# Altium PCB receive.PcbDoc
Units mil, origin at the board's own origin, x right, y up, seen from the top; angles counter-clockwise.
Board outline 787 x 1403 mil, 2 copper layers (Top Layer, Bottom Layer); 26 components, 20 nets, 101 pads, 164 vias.
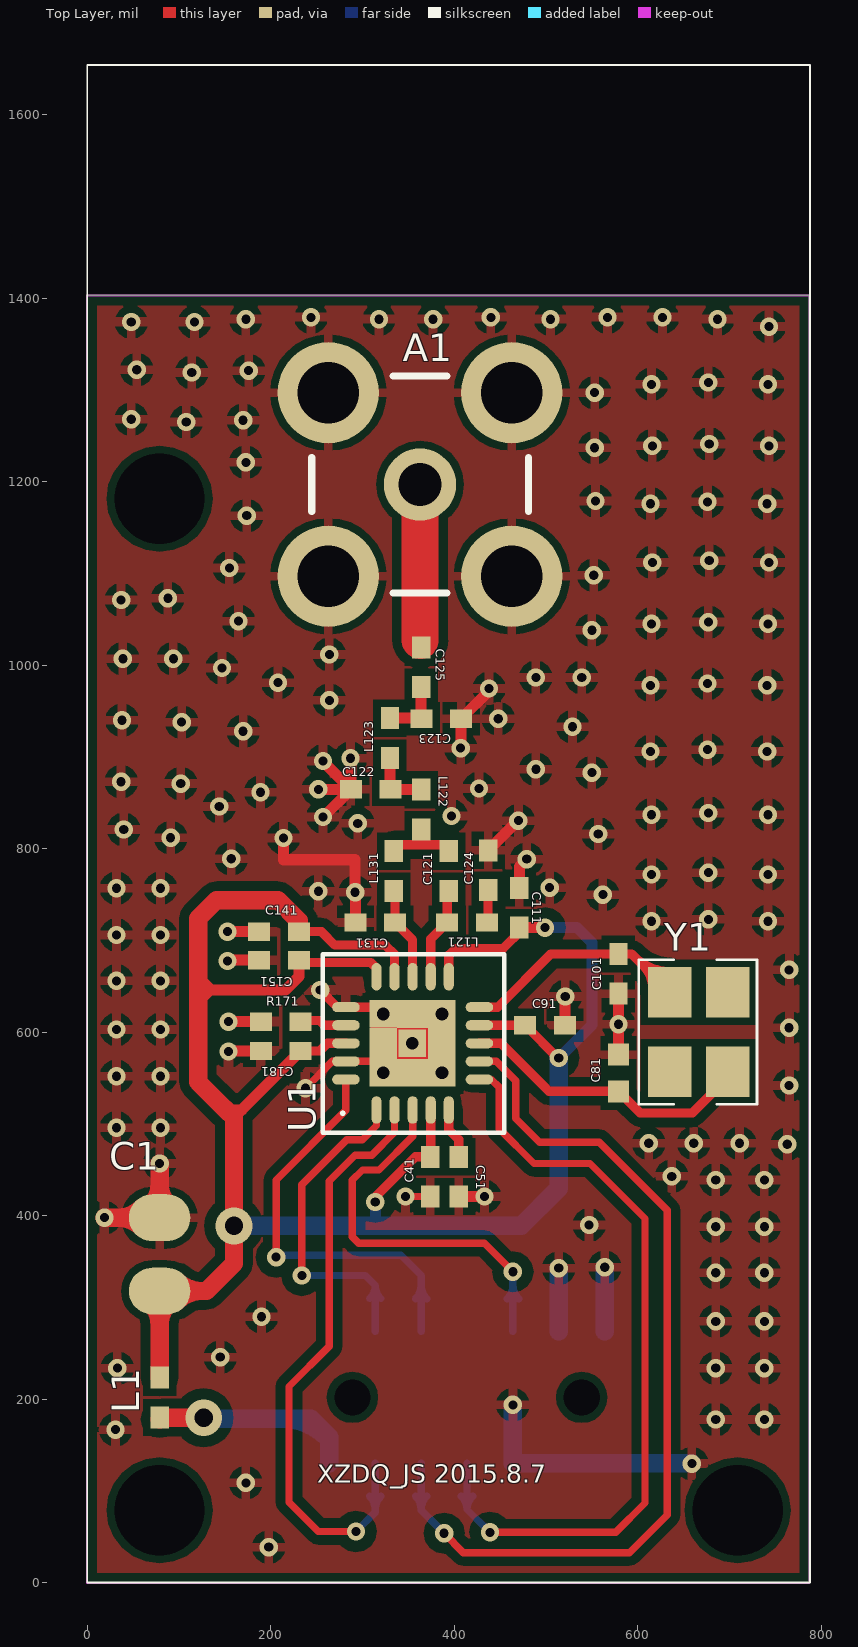
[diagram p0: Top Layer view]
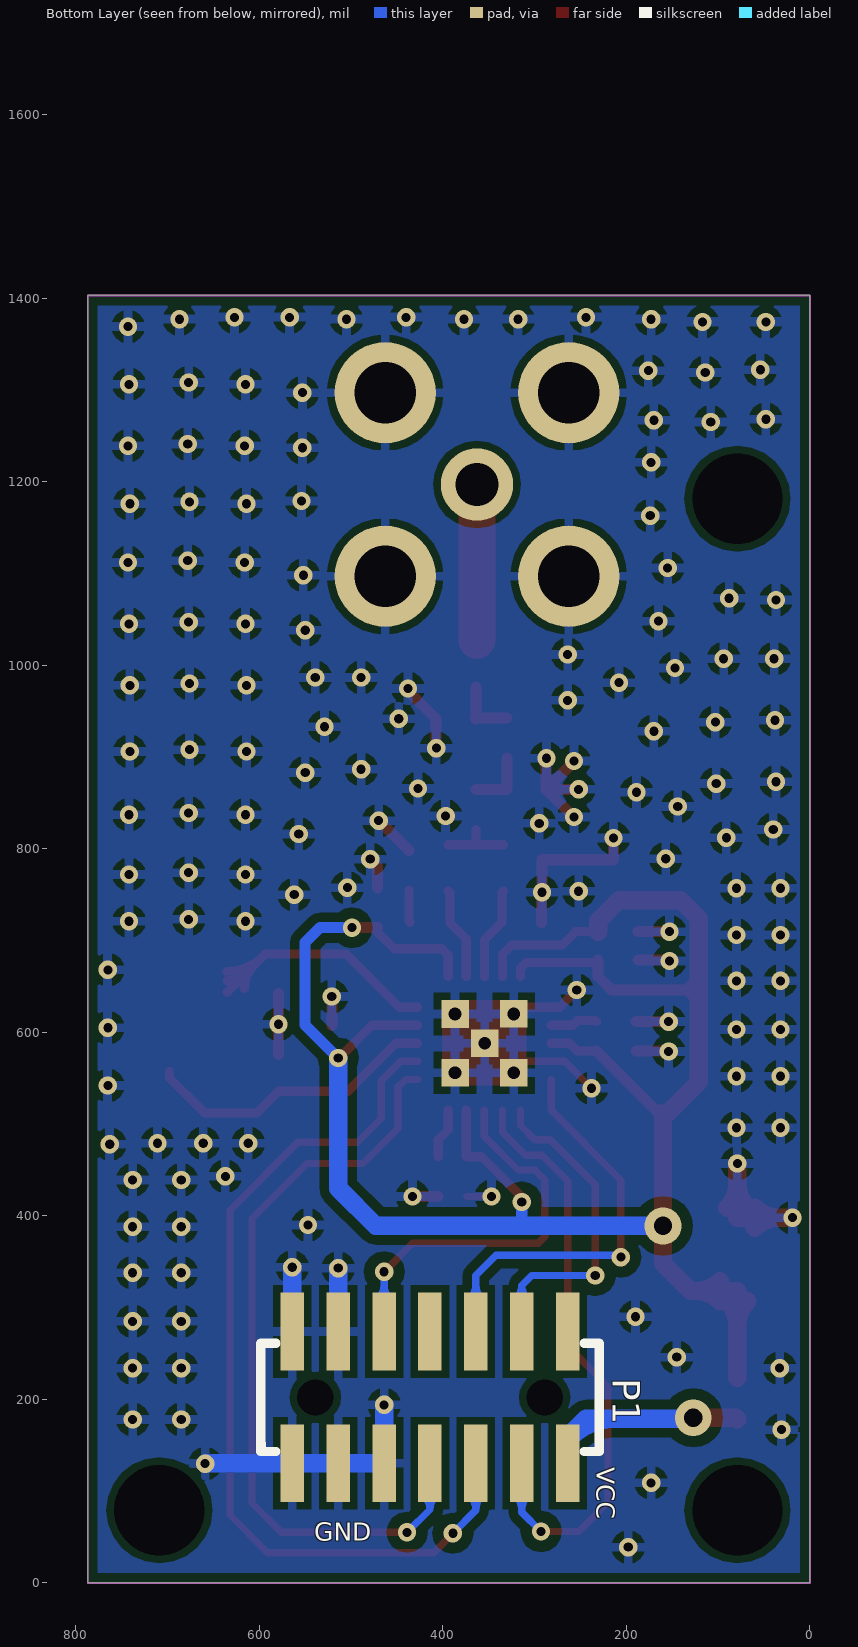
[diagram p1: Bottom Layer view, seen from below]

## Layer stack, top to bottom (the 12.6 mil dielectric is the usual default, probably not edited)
Top Layer: signal copper 1.4
Dielectric: dielectric 12.6, FR-4, Dk 4.8
Bottom Layer: signal copper 1.4

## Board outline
0,0 787,0 787,1403 0,1403

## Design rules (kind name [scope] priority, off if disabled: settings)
Clearance InPolygon_GND_P1 [InNamedPolygon('GND_P1') vs InNet('GND')] p1: gap=8
Clearance InPolygon_GND_P2 [InNamedPolygon('GND_P2') vs InNet('GND')] p2: gap=8
Clearance InPolygon_GND [InNamedPolygon('GND') vs InNet('GND')] p3: gap=8
Clearance "InPolygon_GND layer1" [InNamedPolygon('GND layer1') vs InNet('GND')] p4: gap=8
Clearance CopperToBoard [InPolygon vs (IsTrack Or IsArc) And OnLayer('Keep-out Layer')] p5: gap=10
Clearance ViaToCopper [IsVia vs InPolygon] p6: gap=12
Clearance ViaToVia [IsVia vs IsVia] p7: gap=8
Clearance PadToCopper [IsPad vs InPolygon] p8: gap=8
Clearance PadToVia [IsPad vs IsVia] p9: gap=8
Clearance CPadToPad [IsPad vs IsPad] p10: gap=8
Clearance RouteToPad_1 [IsTrack or IsArc vs IsVia] p11: gap=8
Clearance RouteToPad [IsTrack Or IsArc vs IsPad] p12: gap=8
Clearance RouteToRoute [IsTrack or IsArc vs IsTrack or IsArc] p13: gap=8
Clearance [All] p14: gap=10
ComponentClearance [All] p1: gap=0 collisioncheckmode=3 verticalgap=0 showdistances=FALSE
MinimumSolderMaskSliver [All] p1: minsoldermaskwidth=0
PolygonConnect [All] p1: connectstyle=Relief reliefconductorwidth=10 reliefentries=4 polygonreliefangle="90 Angle"
RoutingVias [All] p1: holewidth=28 width=50 viastyle="Through Hole" minholewidth=10 minwidth=20 maxholewidth=28 maxwidth=50
SilkToSilkClearance [All] p1: silktosilkclearance=0
SilkscreenOverComponentPads [All] p1: minsilkscreentomaskgap=0
SolderMaskExpansion [All] p1: expansion=4
Width [All] p1: maxlimit=60 minlimit=8 preferedwidth=10
24 further rules are at their usual default settings.

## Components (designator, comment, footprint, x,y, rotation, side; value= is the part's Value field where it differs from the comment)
A1 "Antenna" SMA 363,1197 r0 top
C1 "1uF" "0805 (reflow)" 80,358 r90 top
C41 "100nF" "0402 (REFLOW)" 374,442.65 r270 top
C51 "100nF" "0402 (REFLOW)" 405,442.65 r270 top
C81 "12pF" "0402 (REFLOW LF)" 578,555.65 r90 top
C91 "10nF" "0402 (REFLOW)" 499,607.65 r0 top
C101 "15pF" "0402 (REFLOW)" 579,663.65 r270 top
C111 "220pF" "0402 (REFLOW)" 471,735.65 r90 top
C121 "3.9pF" "0402 (REFLOW)" 394,775.65 r90 top
C122 "8.2pF" "0402 (REFLOW)" 309,864.65 r180 top
C123 "5.6pF" "0402 (REFLOW)" 386,941.65 r0 top
C124 "220pF" "0402 (REFLOW)" 437,776.65 r270 top
C125 "220pF" "0402 (REFLOW)" 364,997.65 r90 top
C131 "3.9pF" "0402 (REFLOW)" 314,719.65 r180 top
C141 "10nF" "0402 (REFLOW)" 209,709.65 r180 top
C151 "220pF" "0402 (REFLOW)" 209,678.65 r180 top
C181 "220pF" "0402 (REFLOW)" 211,579.65 r180 top
L1 "LM15HG102SN1D" "0402 (REFLOW)" 79,202 r270 top
L121 "27nH" "0402 (REFLOW)" 414,719.65 r0 top
L122 "22nH" "0402 (REFLOW)" 364,842.65 r270 top
L123 "27nH" "0402 (REFLOW)" 330,920.65 r270 top
L131 "27nH" "0402 (REFLOW)" 334,775.65 r270 top
P1 "Header 7X2" "SFM SMD Socket 2x7 b" 289,202.3 r270 bottom locked
R171 "56K" "0402 (REFLOW)" 211,611.65 r180 top
U1 "CC1101" QLP20/QFN/CC1101 353.18,587.57 r90 top
Y1 "26MHz" "XTAL_SMD_3_2x2_5 (3.2 x 2.5 mm)" 695.99,558.04 r90 top

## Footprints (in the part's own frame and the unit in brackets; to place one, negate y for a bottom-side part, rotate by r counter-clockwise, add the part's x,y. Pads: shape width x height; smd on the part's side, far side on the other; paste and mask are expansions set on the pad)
"0402 (REFLOW LF)" [mil]
  rect 24x23 smd paste+0 mask+6: 1(-20,-1) 2(20,-1)
"0402 (REFLOW)" [mil]
  rect 24x20 smd paste+0 mask+4: 1(-21.65,0) 2(21.65,0)
"0805 (reflow)" [mil]
  oval 51x67 smd paste+0 mask+4: 1(-40,1) 2(40,1)
QLP20/QFN/CC1101 [mil]
  oval 30x11 smd paste-2 mask+2: 1(-72.24,37.83) 2(-72.24,18.14) 3(-72.24,-1.54) 4(-72.24,-21.23) 5(-72.24,-40.91) 11(73.05,-40.91) 12(73.05,-21.23) 13(73.05,-1.54) 14(73.05,18.14) 15(73.05,37.83)
  oval 11x30 smd paste-2 mask+2: 6(-38.97,-74.27) 7(-19.28,-74.27) 8(0.4,-74.27) 9(20.09,-74.27) 10(39.77,-74.27) 16(39.77,71.18) 17(20.09,71.18) 18(0.4,71.18) 19(-19.28,71.18) 20(-38.97,71.18)
  rect 30x30 / inner round 60 / far side rect 30x30 hole 14 paste+0 mask+0: 21(-31.66,30.48) 22(32.37,30.48) 23(-31.66,-33.52) 24(32.34,-33.52) 25(0.4,-1.15)
  rect 34x30 smd paste-13 mask+0: 26(0.34,30.48) 29(0.37,-33.52)
  rect 30x34 smd paste-13 mask+0: 27(32.34,-1.58) 28(-31.66,-1.52)
  silkscreen extent -97,-101 98,96
"SFM SMD Socket 2x7 b" [mm]
  round 0.8 hole 1 unplated: 0(0.003,0) 0(0.004,-6.35)
  rect 2.15x0.65 smd: 1(-1.821,0.635) 2(1.829,0.635) 3(-1.821,-0.635) 4(1.829,-0.635) 5(-1.821,-1.905) 6(1.829,-1.905) 7(-1.821,-3.175) 8(1.829,-3.175) 9(-1.821,-4.445) 10(1.829,-4.445) 11(-1.821,-5.715) 12(1.829,-5.715) 13(-1.821,-6.985) 14(1.829,-6.985)
  silkscreen extent -1.5,-7.86 1.5,1.51
SMA [mm]
  round 2 hole 1.2: 1(-0.005,-0.002)
  round 2.8 hole 1.7: 2(-2.545,-2.542) 3(2.535,-2.542) 4(2.535,2.538) 5(-2.545,2.538)
  silkscreen extent -3.01,-3 2.99,3
"XTAL_SMD_3_2x2_5 (3.2 x 2.5 mm)" [mm]
  rect 1.4x1.2 smd paste-0.06 mask+0.05: 1(-0.025,-0.051) 2(2.175,-0.051) 3(2.175,1.549) 4(-0.025,1.549)
  silkscreen extent -0.93,-0.86 3.07,2.41

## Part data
C1 C41 C51 C81 C91 C101 C111 C121 C122 C123 C124 C125 C131 C141 C151 C181: library part CAP, "CAP"
L1 L121 L122 L123 L131: library part Inductor, "Inductor"
P1: "Header, 7-Pin, Dual row"
R171: library part RES, "RES"
U1: "Single chip transceiver"
Y1: library part XY1, "四脚晶振"

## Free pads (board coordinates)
  round 39.37 hole 98.43: 0(78.96,79.12) 0(78.96,1181.48) 0(708.88,79.12)

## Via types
v1: diameter 20, hole 10, Top Layer to Bottom Layer, 162 vias
v2: diameter 40, hole 20, Top Layer to Bottom Layer, 2 vias

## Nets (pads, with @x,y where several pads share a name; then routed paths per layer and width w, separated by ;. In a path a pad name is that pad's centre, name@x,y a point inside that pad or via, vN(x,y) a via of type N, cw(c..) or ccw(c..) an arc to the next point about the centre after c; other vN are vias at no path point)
230: C81.1 U1.8 Y1.1 | length 324.5
  Top Layer w10: U1.8 451.03,587.97 503.35,535.65 C81.1 602.65,512 659.53,512 697.99,550.47 Y1.1
233: C101.1 U1.10 Y1.3 | length 343.2
  Top Layer w10: U1.10 447.34,627.34 505.31,685.31 C101.1 593.35,685.31 Y1.3 ; 596.49,682.16 ccw(c635,720.67) Y1.3@635,666.21 ; 605.99,672.66 cw(c580.93,647.59) Y1.3@616.38,647.59 ; Y1.3@613.56,665.09 ccw(c635,686.53) Y1.3@635,656.21
246: R171.1 U1.17 | length 52.1
  Top Layer w10: R171.1 234,613 253,613 258.35,607.65 U1.17
254: C122.1 L122.1 L123.2 | length 68.1
  Top Layer w12: L123.2 330,865.31 C122.1 331,864.31 L122.1
255: C123.1 C125.1 L123.1 | length 69.1
  Top Layer w12: L123.1 363.69,942.31 C123.1 364,942 C125.1
256: A1.1 C125.2 | length 171.7
  Top Layer w40: A1.1 362.8,1027.2 C125.2@363,1027
  Top Layer w50: A1.1 A1.1@364,1195.72
275: C51.1 U1.5 | length 55.5
  Top Layer w10: U1.5 394.09,493.91 405,483 C51.1
286: C131.1 L131.2 U1.13 | length 102
  Top Layer w10: L131.2 335.65,752.35 C131.1 354.72,700.58 U1.13
287: C121.2 L122.2 L131.1 | length 76.7
  Top Layer w10: L131.1@334,804.31 C121.2@394,804.31 ; 364,804.31 L122.2
290: C121.1 L121.1 U1.12 | length 101.5
  Top Layer w10: U1.12 374.41,701.72 L121.1 392.35,752.35 C121.1
291: C124.2 L121.2 | length 35.9
  Top Layer w10: L121.2 437,721 C124.2
CC1101_CSN: P1.6 U1.7 | length 1016.5
  Top Layer w8: v1(389,54) 410,33 419,33 591,33 632,74 632,406 558,480 493,480 467,506 467,547 445.72,568.28 U1.7
  Bottom Layer w8: P1.6@357.78,94.55 cw(c342.77,79.54) 364,79.54 cw(c385.23,79.54) P1.6@370.22,94.55 ; P1.6 364,79 v1(389,54)
CC1101_GDO0: P1.8 U1.6 | length 879.9
  Top Layer w8: U1.6 440.4,548.6 449,540 449,495 487,457 548,457 608,397 608,87 576,55 v1(439,55)
  Bottom Layer w8: P1.8@407.88,94.46 cw(c393.87,80) 414,80 ; P1.8 414,80 ; P1.8@420.12,94.46 ccw(c434.13,80) 414,80 ; v1(439,55) 414,80
CC1101_GDO2: P1.9 U1.3 | length 465.2
  Top Layer w8: U1.3 354.72,486.72 318,450 300,450 289,439 289,377 296,370 430,370 433,370 v1(464,339)
  Bottom Layer w8: P1.9@457.78,309.75 ccw(c442.77,324.76) 464,324.76 ccw(c485.23,324.76) P1.9@470.22,309.75 ; P1.9 v1(464,339)
CC1101_SCLK: P1.3 U1.1 | length 390.1
  Top Layer w8: v1(234,335) 234,434 283,483 300,483 315.35,498.35 U1.1
  Bottom Layer w8: v1(234,335) 303,335 314,324 ; P1.3@307.95,309.91 ccw(c294.57,324) 314,324 ; P1.3 314,324 ; P1.3@320.05,309.91 cw(c333.43,324) 314,324
CC1101_SI: P1.5 U1.20 | length 487.4
  Top Layer w8: v1(206,355) 206,439 282,515 U1.20
  Bottom Layer w8: v1(206,355) 208,357 342,357 364,335 P1.5 ; P1.5@357.78,309.75 ccw(c342.77,324.76) 364,324.76 ccw(c385.23,324.76) P1.5@370.22,309.75
CC1101_SO: P1.4 U1.2 | length 688.1
  Top Layer w8: v1(293,56) 252,56 220,88 220,214 264,258 264,365 264,438 292,466 310,466 335.04,491.04 U1.2
  Bottom Layer w8: v1(293,56) 314,77 P1.4 ; P1.4@307.78,94.55 cw(c292.77,79.54) 314,79.54 cw(c335.23,79.54) P1.4@320.22,94.55
GND: A1.2 A1.3 A1.4 A1.5 C1.2 C41.2 C51.2 C81.2 C91.2 C101.2 C111.2 C122.2 C123.2 C124.1 C131.2 C141.2 C151.2 C181.2 P1.10 P1.11 P1.12 P1.13 P1.14 R171.2 U1.16 U1.19 U1.21 U1.22 U1.23 U1.24 U1.25 U1.26 U1.27 U1.28 U1.29 | length 1593.6
  Top Layer w8: v1(238,539) 267.28,568.28 U1.19 310.32,568.28 U1.21 ; v1(347,421) C41.2
  Top Layer w10: v1(254,646) 272.66,627.34 U1.16 315.3,627.34 U1.22
  Top Layer w12: v1(153,677.65) 154,678.65 C151.2 ; v1(153,709.65) C141.2 ; v1(154,579) 154.65,579.65 C181.2 ; v1(154,611.65) R171.2 ; v1(214,811.65) 214,788 292,788 v1(292,752.65) 292.35,752.31 C131.2 ; v1(252,864.65) C122.2 ; v1(257,834.65) 257.35,834.65 C122.2 ; v1(257,895.65) 257,895 C122.2 ; v1(287,898.65) 287.35,898.31 C122.2 ; C51.2 v1(433,421) ; v1(407,909.65) 407.65,910.31 C123.2 438,972 v1(438,974.65) ; C124.1 469.35,830.65 v1(470,830.65) ; C111.2 471,780.65 v1(479,788.65) ; C91.2 520.65,638.65 v1(521,639) ; C81.2 v1(579,608.65) C101.2
  Top Layer w20: v1(19,398) C1.2 v1(79,457) ; C1.2@60.04,387.04 ccw(c33.58,360.58) 33.58,398 ccw(c33.58,435.42) C1.2@60.04,408.96 ; C1.2@68.04,408.96 ccw(c41.58,435.42) 79,435.42 ccw(c116.42,435.42) C1.2@89.96,408.96
  Bottom Layer w20: v1(464,194) P1.10 P1.14 658.7,130.3 v1(659,130) ; P1.11 v1(514,343) ; P1.13 v1(564,344)
  other v1: 198,39 173,109 31,167 685,178 738,178 33,234 685,234 738,234 145,246 685,285 738,285 190,290 685,338 738,338 685,388 738,388 547,390 685,439 738,439 637,443 763,478 612,479 661,479 711,479 32,496 80,496 765,542 32,552 80,552 32,603 80,603 765,605 32,656 80,656 765,668 32,706 80,706 615,721 742,721 677,723 562,750 252,753.65 32,757 80,757 504,757.65 615,772 742,772 677,774 157,789 91,812 557,816 40,821 295,827.65 397,835.65 615,837 742,837 677,839 144,846 189,861.65 427,865.65 102,871 37,873 550,883 489,886.65 614,906 741,906 676,908 170,928 529,933 103,938 38,940 448,941.65 264,961.65 614,978 741,978 676,980 208,981 489,986.65 539,986.65 147,997 39,1007 94,1007 264,1011.65 550,1038 615,1045 742,1045 677,1047 165,1048 37,1071 88,1073 552,1098 155,1106 616,1112 743,1112 678,1114 174,1163 614,1176 741,1176 676,1178 554,1179 173,1221 553,1237 616,1239 743,1239 678,1241 108,1265 170,1267 48,1268 553,1297 615,1306 742,1306 677,1308 114,1319 176,1321 54,1322 743,1369 48,1374 117,1374 173,1377 318,1377 377,1377 505,1377 687,1377 244,1379 440,1379 567,1379 627,1379
VCC: L1.2 P1.2 | length 279.4
  Top Layer w20: L1.2@79,178.35 80.65,180 v2(127,180)
  Bottom Layer w20: v2@127,179 244,179 264,159 P1.2 ; 210.96,179 cw(c210.96,106.79) P1.2@262.02,157.85
VDD: C1.1 C41.1 C91.1 C111.1 C141.1 C151.1 C181.1 L1.1 U1.4 U1.9 U1.11 U1.14 U1.15 U1.18 | length 2571.9
  Top Layer w10: C151.1 233.31,676 309,676 315.35,669.65 U1.15 ; C141.1 255.35,709.65 270,695 325,695 335.04,684.96 U1.14 ; C181.1 253.65,579.65 261.97,587.97 U1.18 ; v1(314,415) 314,420.53 357.78,464.31 C41.1 374.41,464.72 U1.4 ; U1.11 394.09,684.09 401,691 453,691 C111.1@474,712 ; U1.9 C91.1 513,572 v1(514,572)
  Top Layer w12: 121,633 134,646 139,646 ; 121,646 139,646 ; 121,660 135,646 139,646 ; 151.5,515.5 168.5,515.5 170.5,517.5 ; 160,507 C181.1 ; C151.1 230.65,660.65 216,646 139,646 ; C111.1 v1(499,714)
  Top Layer w20: C1.1@68.04,307.04 cw(c41.58,280.58) 79,280.58 cw(c116.42,280.58) C1.1@89.96,307.04 ; L1.1 C1.1 ; C1.1@97.96,307.04 cw(c124.42,280.58) 124.42,318 cw(c124.42,355.42) C1.1@97.96,328.96 ; C1.1@103,318 C1.1 ; C141.1 230.65,721.35 208,744 141,744 121,724 121,646 121,546 151.5,515.5 160,507 v2(160,389) 160,348 130,318 C1.1
  Bottom Layer w12: v1(314,415) 314,394 319,389 ; v1(499,714) 534,714 550,698 550,608 v1(514,572)
  Bottom Layer w20: v2(160,389) 319,389 473,389 514,430 v1(514,572)
pads on no net: P1.0 P1.1 P1.7 Y1.2 Y1.4

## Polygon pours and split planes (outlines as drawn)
GND on Top Layer "GND layer1" (solid, remove dead copper, pour order 1000): 0,1403 787,1403 787,0 0,0 0,1403
GND on Bottom Layer "GND" (solid, remove dead copper, pour order 1001): 0,1403 787,1403 787,0 0,0 0,1403

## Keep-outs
Keep-Out Layer:
  the board outline again, w2

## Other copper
Top Layer:
  rectangle net GND: 309,542 401,635

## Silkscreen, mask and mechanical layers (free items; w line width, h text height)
Top Overlay:
  lines w2: 0.22,0.38 787.62,0.38 787.62,1653.92 0.22,1653.92 0.22,0.38
  text "XZDQ_JS 2015.8.7" at 251,109 h20
Bottom Overlay:
  text "VCC" at 232,126 h20 r90
  text "GND" at 540,46 h20

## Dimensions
787,1403 to 787,0 on Top Overlay
0,0 to 787,0 on Top Overlay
